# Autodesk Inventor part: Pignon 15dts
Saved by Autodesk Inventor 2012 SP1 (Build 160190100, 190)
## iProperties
Created: 2014-12
Part Number: Pignon 15dts
Material: Default
Document SubType Name: Modeling
Designer: Bruno
Density: 1 g/cm^3
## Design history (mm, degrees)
node "Pignon 15dts1"
node "Pignon 15dts"
node "Base1"
